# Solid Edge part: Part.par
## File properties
Author: TIET
Template: iso metric part.par
Last saved by: Rajat Kamboj
Revision: 2
Application: Solid Edge
Accuracy: 0.990
Username: TIET
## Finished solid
Body 1: solid body, 34 faces, 81 edges, 46 vertices.
  Faces by surface: plane 28, cylinder 6
  Edges by curve: line 67, circle 14
Bounding box of the edges (mm): 92.000 x 170.000 x 106.000, from (-46, -30, -30) to (46, 140, 76).
Cylindrical faces by radius (mm): R8 x2, R16 x2, R18 x1, R30 x1
Planar faces by outward normal: +x 5, +y 3, +z 4, -x 5, -y 5, -z 4, oblique 2
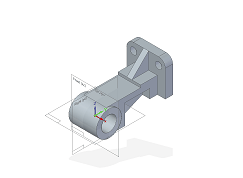
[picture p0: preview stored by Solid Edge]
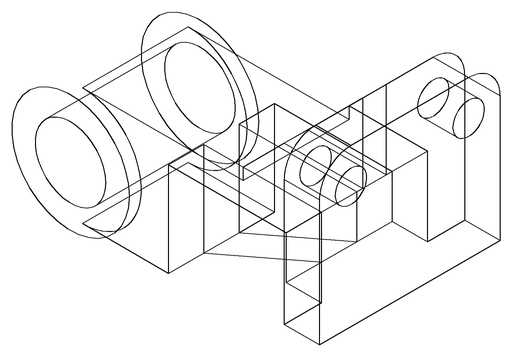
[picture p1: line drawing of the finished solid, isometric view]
